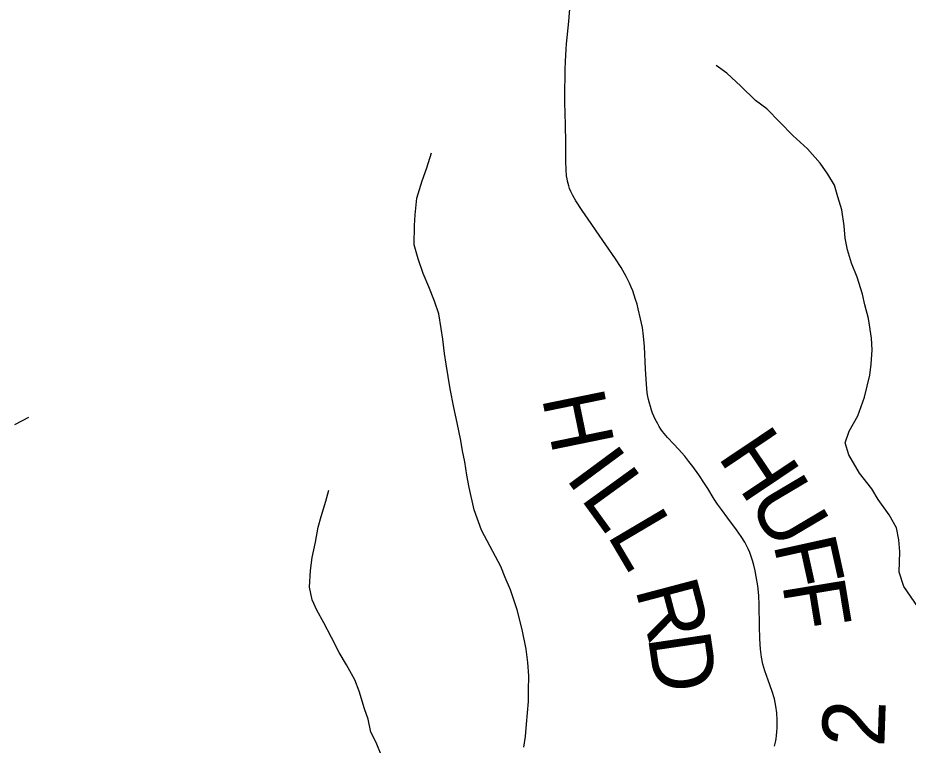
# Model space of a CAD drawing. Extents: x 1451455 to 1749751, y 218250 to 574981.
# Drawn here: x 1620554 to 1624828, y 290686 to 294178 of the extents above; entities that cross this region are included whole.
import ezdxf

# ---------------------------------------------------------------- set-up
doc = ezdxf.new("R2010")
doc.units = 0
for name, color, linetype in [('GM_X_County_Road', 7, 'Continuous'), ('GM_X_County_Road_Text', 7, 'Continuous'), ('GM_X_Minor_River', 7, 'Continuous')]:
    doc.layers.add(name, color=color, linetype=linetype)

msp = doc.modelspace()

# ---------------------------------------------------------------- linework, layer by layer
at = {"layer": 'GM_X_County_Road'}
msp.add_lwpolyline([(1624186.3, 290680.6), (1624190.4, 290700.2), (1624193.2, 290715.8), (1624195.5, 290732.8), (1624197.1, 290749.6), (1624198.5, 290768.9), (1624198.8, 290805.1), (1624196.7, 290841.1), (1624192.5, 290873.6), (1624185.4, 290908.8), (1624175.3, 290943.3), (1624155.2, 290998), (1624138.8, 291043.4), (1624130.1, 291074.3), (1624123.1, 291108.9), (1624118.6, 291147.4), (1624115, 291195.9), (1624113.4, 291257.7), (1624112.7, 291359), (1624110.6, 291404.9), (1624106, 291450.6), (1624098.6, 291496), (1624092.6, 291523.3), (1624086.2, 291550.3), (1624080, 291571.9), (1624074, 291591.3), (1624067.2, 291610.5), (1624060, 291628.2), (1624052.2, 291644.6), (1624043.7, 291660.6), (1624026.1, 291688.3), (1624003.4, 291720.3), (1623962.5, 291775.1), (1623931.4, 291816.6), (1623912.6, 291843.2), (1623896.4, 291867.6), (1623865.3, 291917.4), (1623849.6, 291942.4), (1623822.3, 291983.5), (1623793.7, 292023.8), (1623774.9, 292048.4), (1623755.1, 292073), (1623724.7, 292107.8), (1623702.1, 292131.7), (1623672.8, 292162.3), (1623656.2, 292182.3), (1623648.6, 292192.2), (1623640.9, 292203.2), (1623632.9, 292215.7), (1623625.5, 292227.9), (1623618.9, 292239.1), (1623613.5, 292250.8), (1623606.9, 292264.8), (1623600.5, 292280.5), (1623595.2, 292294.8), (1623589.9, 292311.1), (1623585.1, 292327.7), (1623580.9, 292345.6), (1623577.9, 292360.5), (1623575.4, 292377.6), (1623572.7, 292399), (1623570.9, 292419.7), (1623566.2, 292491.5), (1623561.4, 292599.8), (1623557.4, 292649), (1623551.6, 292691.5), (1623543.3, 292733.6), (1623531.8, 292781.6), (1623525.9, 292803.8), (1623519.1, 292826), (1623512.4, 292846.8), (1623505.1, 292866.5), (1623498.1, 292885.4), (1623490.1, 292903.3), (1623474.2, 292936), (1623449.9, 292979), (1623423.3, 293020.7), (1623329.8, 293155.4), (1623305.3, 293190.3), (1623263.1, 293252.7), (1623232.5, 293299.1), (1623218, 293324.4), (1623208.3, 293344.8), (1623202.5, 293358.9), (1623198, 293371.9), (1623192.2, 293393.6), (1623190, 293405.8), (1623187.8, 293419), (1623185.3, 293448), (1623184.5, 293490.4), (1623183.5, 293578.9), (1623182.4, 293664.3), (1623180.2, 293772.4), (1623179.8, 293834.8), (1623180.3, 293890.4), (1623180.8, 293929.7), (1623182.2, 293968.8), (1623185.6, 294027.5), (1623187.7, 294053.6), (1623197.9, 294161.2), (1623204.8, 294242.8)], dxfattribs=at)
at = {"layer": 'GM_X_Minor_River'}
for points in [[(1624873.2, 291350), (1624806.2, 291446.9), (1624785, 291517.2), (1624788.1, 291613.3), (1624782.8, 291671.4), (1624771.4, 291729.6), (1624736.1, 291792.1), (1624682.9, 291864.8), (1624653.4, 291917.1), (1624594.2, 291991.9), (1624543.2, 292080.5), (1624525.8, 292136.8), (1624544.5, 292192.7), (1624585.3, 292266.3), (1624618.4, 292356), (1624643.6, 292461.9), (1624650.2, 292515.9), (1624655, 292583.9), (1624651.6, 292640), (1624636.7, 292734.3), (1624619.4, 292800.5), (1624608, 292850.7), (1624582.9, 292933.1), (1624555.6, 292999.5), (1624536.4, 293063.7), (1624525, 293119.9), (1624519.7, 293180.1), (1624508.5, 293256.3), (1624489.2, 293318.5), (1624473.8, 293374.8), (1624442.4, 293427.2), (1624405, 293479.6), (1624343.7, 293548.4), (1624274.4, 293613.2), (1624149.7, 293740.8), (1624094.1, 293781.4), (1624024.9, 293850.2), (1623957.5, 293913.1), (1623905.9, 293949.7)], [(1622982, 290676.1), (1622990.6, 290728.1), (1622995.2, 290786.1), (1623004.5, 290896.1), (1623005.1, 290948.2), (1623005.9, 291018.2), (1623002.6, 291082.4), (1622993.3, 291146.5), (1622974.4, 291240.9), (1622951.4, 291335.2), (1622918.5, 291431.7), (1622893.1, 291490.1), (1622871.7, 291544.4), (1622820.7, 291639.1), (1622779.6, 291717.6), (1622744.7, 291816.1), (1622719.9, 291922.5), (1622708.5, 291982.7), (1622699.2, 292046.9), (1622687.8, 292099.1), (1622680.4, 292149.2), (1622663.3, 292233.5), (1622646.2, 292307.8), (1622629.1, 292396.1), (1622610.5, 292514.4), (1622601.1, 292566.6), (1622593.8, 292634.7), (1622586.4, 292686.9), (1622575.2, 292757.1), (1622553.9, 292817.4), (1622526.6, 292885.8), (1622499.3, 292950.1), (1622476.1, 293020.5), (1622456.9, 293088.8), (1622457.9, 293180.8), (1622460.5, 293232.9), (1622469.4, 293312.8), (1622494.4, 293394.7), (1622517.1, 293458.5), (1622540, 293530.3)], [(1620539.4, 292224.9), (1620605.9, 292260.2)], [(1622300.9, 290631.5), (1622273.6, 290697.9), (1622248.2, 290748.3), (1622234.9, 290810.5), (1622217.4, 290860.8), (1622192.4, 290945.1), (1622170.9, 290999.4), (1622131.7, 291072), (1622096.4, 291130.4), (1622059.2, 291202.9), (1622021.9, 291273.4), (1621988.6, 291333.9), (1621967.1, 291384.2), (1621953.8, 291444.4), (1621958.7, 291524.4), (1621967.4, 291586.4), (1621982.3, 291660.3), (1621995.1, 291732.3), (1622009.7, 291784.2), (1622032.5, 291858), (1622047.1, 291909.9)]]:
    msp.add_lwpolyline(points, dxfattribs=at)

# ---------------------------------------------------------------- texts
at = {"layer": 'GM_X_County_Road_Text'}
for s, rotation, p in [('H', 281.5825, (1623068.1, 292356.3)), ('H', 303.8406, (1623909, 292072.8)), ('I', 306.4953, (1623177.7, 291970.7)), ('L', 305.93, (1623250.5, 291872.3)), ('U', 300.6829, (1624053.7, 291857.2)), ('L', 300.5933, (1623378.1, 291696.8)), ('F', 282.4809, (1624179.2, 291653.5)), ('R', 284.8205, (1623515.8, 291437)), ('F', 279.3256, (1624222.1, 291460.2)), ('D', 278.3606, (1623577.1, 291207.5)), ('2', 88.0251, (1624712.6, 290674.1))]:
    msp.add_text(s, height=300, rotation=rotation, dxfattribs=at).set_placement(p)

doc.saveas('drawing.dxf')
